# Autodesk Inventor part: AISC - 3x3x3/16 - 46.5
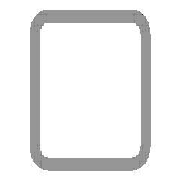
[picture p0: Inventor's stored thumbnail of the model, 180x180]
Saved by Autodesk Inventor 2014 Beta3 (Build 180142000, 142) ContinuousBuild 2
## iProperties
IsCustomPart: 1
Created: 2011-01
Part Number: AISC - 3x3x3/16 - 46.5
Material: Steel, Mild
Description: Tube
Document SubType Name: Modeling
Standard: ANSI
Designer: Beta-8540w
Standards Organization: ANSI
Language: en-US
Size Designation: 3x3x3/16
Categories: <MemberInstance><Categories><Category DisplayName="Structural Shapes" InternalName="089c4875-fa83-4c05-b084-43b9cc11f5ed" Mnemonic="GRDR"><CategoryParameter Dis
Stock Number: 3x3x3/16
Density: 7.86 g/cm^3
Appearance: Steel
_CCFamilyMember: 9
_CCFamilyDisplayName: ANSI AISC (Square) - Tube
_FrameMemberDoc: Frame Member File
_Version: 15.0.0
_GetPNFromCC: 1
G_L: 46.500 in
G_W: 3.000 in
G_H: 3.000 in
Author: Beta-8540w
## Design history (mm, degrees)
node "Start plane"
node "End plane"
sketch "Sketch"
  geometry: L1 (-38.1, -28.575)-(-38.1, 28.575); L2 (-28.575, 38.1)-(28.575, 38.1); L3 (38.1, 28.575)-(38.1, -28.575); L4 (28.575, -38.1)-(-28.575, -38.1); L5 (-28.575, 33.337)-(28.575, 33.338); L6 (33.338, 28.575)-(33.338, -28.575); L7 (28.575, -33.337)-(-28.575, -33.338); L8 (-33.338, -28.575)-(-33.338, 28.575); L9 (0, 56.102)-(0, -56.102) reference; L10 (-56.102, 0)-(56.102, 0) reference; A1 r 9.525 centre (-28.575, -28.575) between (-38.1, -28.575) and (-28.575, -38.1); A2 r 9.525 centre (-28.575, 28.575) between (-28.575, 38.1) and (-38.1, 28.575); A3 r 9.525 centre (28.575, 28.575) between (38.1, 28.575) and (28.575, 38.1); A4 r 9.525 centre (28.575, -28.575) between (28.575, -38.1) and (38.1, -28.575); A5 r 4.763 centre (-28.575, 28.575) between (-28.575, 33.337) and (-33.338, 28.575); A6 r 4.763 centre (28.575, 28.575) between (33.338, 28.575) and (28.575, 33.338); A7 r 4.763 centre (28.575, -28.575) between (28.575, -33.337) and (33.338, -28.575); A8 r 4.763 centre (-28.575, -28.575) between (-33.338, -28.575) and (-28.575, -33.338)
  constraints: 16 end point, 16 point on circle, 8 centre point, 8 tangent, 4 parallel, 3 equal radius, 2 perpendicular, 7 other
  dimensions: "d10" = 76.2 distance between parallel lines of L2 L4 (= G_H); "d11" = 76.2 distance between parallel lines of L1 L3 (= G_W); "d12" = 4.7625 distance between parallel lines of L3 L6 (= G_T); "d15" = 38.1 distance between parallel lines of L2 L10 (= 0.5 x d10); "d16" = 38.1 distance between parallel lines of L9 L3 (= 0.5 x d11); "d17" = 9.525 radius of A1 (= G_IR)
extrude "Body" new body sketch "Sketch" stored distance "d3" = 1181.1 (= G_L); taper "d4" = 0 deg
node "Driven Length"
  sketch "Sketch3"
    geometry: L1 (0, 0)-(10, 0) reference
    constraints: 2 end point, 1 horizontal
  workplane "Work Plane3"
  sketch "Sketch4"
    geometry: L1 (-2, 0)-(12, 0) reference; L2 (-2, 1181.1)-(12, 1181.1) reference
    dimensions: "d19" = 1181.1 distance between parallel lines of L1 L2 (derived)
workplane "Work Plane4"
split "Split1"
body "Solid1"
other parameters: "G_W" = 76.2 [user parameter; used in 1 equation term], "G_H" = 76.2 [user parameter; used in 1 equation term], "G_T" = 4.7625 [user parameter; used in 1 equation term], "G_IR" = 9.525 [user parameter; used in 1 equation term], "G_L" = 1181.1 (= d19) [user parameter; used in 1 equation term], "G_OFFSET_START" = 0 [user parameter; used in 1 equation term], "G_OFFSET_END" = -38.1 [user parameter; used in 1 equation term], "d13" = 0 (computed from G_OFFSET_START), "d14" = 1181.1 (= G_OFFSET_END + B_L), "B_L" = 1219.2 [user parameter; used in 1 equation term], "d18" = 90 deg
